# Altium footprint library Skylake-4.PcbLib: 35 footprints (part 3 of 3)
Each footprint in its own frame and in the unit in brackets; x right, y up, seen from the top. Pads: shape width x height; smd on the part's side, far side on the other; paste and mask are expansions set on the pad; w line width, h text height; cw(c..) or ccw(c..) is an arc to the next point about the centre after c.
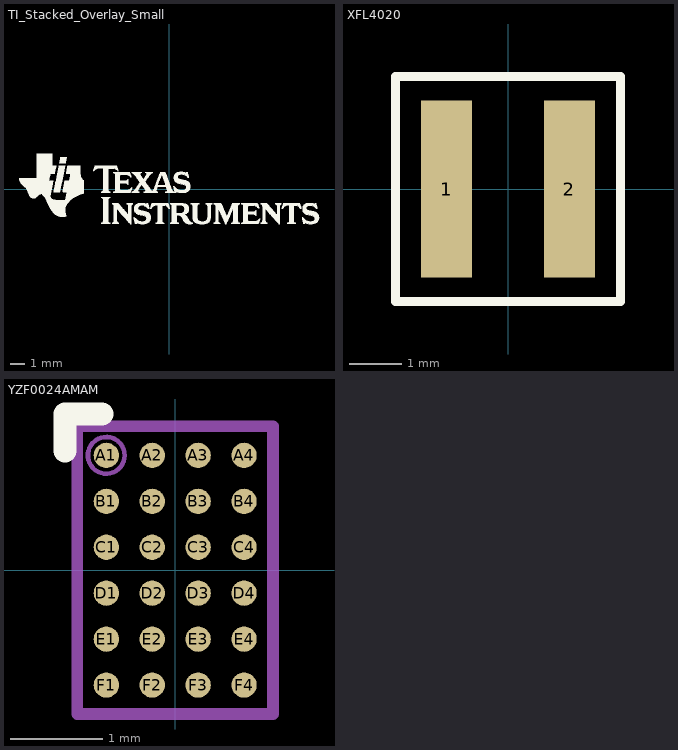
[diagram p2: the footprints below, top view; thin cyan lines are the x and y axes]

## TI_Stacked_Overlay_Small [mm]
Top Overlay:
  drawing of 18 lines, arcs and shapes, not listed

## XFL4020 [mm] "Coilcraft XFL4020 7/18/12"
height 2.1
pads (2):
  rect 0.98x3.4 smd: 1(-1.181,0) 2(1.181,0)
Top Overlay:
  lines w0.17: -2.159,-2.159 -2.159,2.159 2.159,2.159 2.159,-2.159 -2.159,-2.159
Mechanical 5:
  lines w0.1: -2.146,-2.146 -2.146,2.146 2.146,2.146 2.146,-2.146 -2.146,-2.146
  text ".Designator" at 0.504,0.319 h0.76
3D body: height 2.1, standoff 0, extent -2.146,-2.146 2.146,2.146
3D body: height 2.1, standoff 2.03, extent 1.398,-1.269 1.65,1.269

## YZF0024AMAM [mm] "WCSP"
height 0.625
pads (24):
  round 0.275 smd paste-0.15 mask+0.05: A1(-0.75,1.25) A2(-0.25,1.25) A3(0.25,1.25) A4(0.75,1.25) B1(-0.75,0.75) B2(-0.25,0.75) B3(0.25,0.75) B4(0.75,0.75) C1(-0.75,0.25) C2(-0.25,0.25) C3(0.25,0.25) C4(0.75,0.25) D1(-0.75,-0.25) D2(-0.25,-0.25) D3(0.25,-0.25) D4(0.75,-0.25) E1(-0.75,-0.75) E2(-0.25,-0.75) E3(0.25,-0.75) E4(0.75,-0.75) F1(-0.75,-1.25) F2(-0.25,-1.25) F3(0.25,-1.25) F4(0.75,-1.25)
Top Overlay:
  lines w0.254: -1.2,1.3 -1.2,1.7 -0.8,1.7
Top Paste:
  circle w0.05: c0.65,0.35 r0.025
  circle w0.05: c0.85,0.35 r0.025
  circle w0.05: c0.85,0.15 r0.025
  circle w0.05: c0.65,0.15 r0.025
  circle w0.05: c0.15,0.35 r0.025
  circle w0.05: c0.35,0.35 r0.025
  circle w0.05: c0.35,0.15 r0.025
  circle w0.05: c0.15,0.15 r0.025
  circle w0.05: c-0.35,0.35 r0.025
  circle w0.05: c-0.15,0.35 r0.025
  circle w0.05: c-0.15,0.15 r0.025
  circle w0.05: c-0.35,0.15 r0.025
  circle w0.05: c-0.65,0.15 r0.025
  circle w0.05: c-0.85,0.15 r0.025
  circle w0.05: c-0.85,0.35 r0.025
  circle w0.05: c-0.65,0.35 r0.025
  circle w0.05: c-0.65,0.85 r0.025
  circle w0.05: c-0.85,0.85 r0.025
  circle w0.05: c-0.85,0.65 r0.025
  circle w0.05: c-0.65,0.65 r0.025
  circle w0.05: c-0.35,0.65 r0.025
  circle w0.05: c-0.15,0.65 r0.025
  circle w0.05: c-0.15,0.85 r0.025
  circle w0.05: c-0.35,0.85 r0.025
  circle w0.05: c0.15,0.65 r0.025
  circle w0.05: c0.35,0.65 r0.025
  circle w0.05: c0.35,0.85 r0.025
  circle w0.05: c0.15,0.85 r0.025
  circle w0.05: c0.65,0.65 r0.025
  circle w0.05: c0.85,0.65 r0.025
  circle w0.05: c0.85,0.85 r0.025
  circle w0.05: c0.65,0.85 r0.025
  circle w0.05: c-0.65,1.35 r0.025
  circle w0.05: c-0.85,1.35 r0.025
  circle w0.05: c-0.85,1.15 r0.025
  circle w0.05: c-0.65,1.15 r0.025
  circle w0.05: c-0.35,1.15 r0.025
  circle w0.05: c-0.15,1.15 r0.025
  circle w0.05: c-0.15,1.35 r0.025
  circle w0.05: c-0.35,1.35 r0.025
  circle w0.05: c0.15,1.15 r0.025
  circle w0.05: c0.35,1.15 r0.025
  circle w0.05: c0.35,1.35 r0.025
  circle w0.05: c0.15,1.35 r0.025
  circle w0.05: c0.65,1.15 r0.025
  circle w0.05: c0.85,1.15 r0.025
  circle w0.05: c0.85,1.35 r0.025
  circle w0.05: c0.65,1.35 r0.025
  circle w0.05: c0.65,-1.35 r0.025
  circle w0.05: c0.85,-1.35 r0.025
  circle w0.05: c0.85,-1.15 r0.025
  circle w0.05: c0.65,-1.15 r0.025
  circle w0.05: c0.15,-1.35 r0.025
  circle w0.05: c0.35,-1.35 r0.025
  circle w0.05: c0.35,-1.15 r0.025
  circle w0.05: c0.15,-1.15 r0.025
  circle w0.05: c-0.35,-1.35 r0.025
  circle w0.05: c-0.15,-1.35 r0.025
  circle w0.05: c-0.15,-1.15 r0.025
  circle w0.05: c-0.35,-1.15 r0.025
  circle w0.05: c-0.65,-1.15 r0.025
  circle w0.05: c-0.85,-1.15 r0.025
  circle w0.05: c-0.85,-1.35 r0.025
  circle w0.05: c-0.65,-1.35 r0.025
  circle w0.05: c0.65,-0.85 r0.025
  circle w0.05: c0.85,-0.85 r0.025
  circle w0.05: c0.85,-0.65 r0.025
  circle w0.05: c0.65,-0.65 r0.025
  circle w0.05: c0.15,-0.85 r0.025
  circle w0.05: c0.35,-0.85 r0.025
  circle w0.05: c0.35,-0.65 r0.025
  circle w0.05: c0.15,-0.65 r0.025
  circle w0.05: c-0.35,-0.85 r0.025
  circle w0.05: c-0.15,-0.85 r0.025
  circle w0.05: c-0.15,-0.65 r0.025
  circle w0.05: c-0.35,-0.65 r0.025
  circle w0.05: c-0.65,-0.65 r0.025
  circle w0.05: c-0.85,-0.65 r0.025
  circle w0.05: c-0.85,-0.85 r0.025
  circle w0.05: c-0.65,-0.85 r0.025
  circle w0.05: c-0.65,-0.35 r0.025
  circle w0.05: c-0.85,-0.35 r0.025
  circle w0.05: c-0.85,-0.15 r0.025
  circle w0.05: c-0.65,-0.15 r0.025
  circle w0.05: c-0.35,-0.15 r0.025
  circle w0.05: c-0.15,-0.15 r0.025
  circle w0.05: c-0.15,-0.35 r0.025
  circle w0.05: c-0.35,-0.35 r0.025
  circle w0.05: c0.15,-0.15 r0.025
  circle w0.05: c0.35,-0.15 r0.025
  circle w0.05: c0.35,-0.35 r0.025
  circle w0.05: c0.15,-0.35 r0.025
  circle w0.05: c0.65,-0.15 r0.025
  circle w0.05: c0.85,-0.15 r0.025
  circle w0.05: c0.85,-0.35 r0.025
  circle w0.05: c0.65,-0.35 r0.025
  rectangle: 0.6,0.15 0.9,0.35
  region: 0.85,0.1 0.85,0.4 0.65,0.4 0.65,0.1
  rectangle: 0.1,0.15 0.4,0.35
  region: 0.35,0.1 0.35,0.4 0.15,0.4 0.15,0.1
  rectangle: -0.4,0.15 -0.1,0.35
  region: -0.15,0.1 -0.15,0.4 -0.35,0.4 -0.35,0.1
  region: -0.65,0.1 -0.65,0.4 -0.85,0.4 -0.85,0.1
  region: -0.6,0.35 -0.9,0.35 -0.9,0.15 -0.6,0.15
  region: -0.6,0.85 -0.9,0.85 -0.9,0.65 -0.6,0.65
  region: -0.65,0.6 -0.65,0.9 -0.85,0.9 -0.85,0.6
  region: -0.15,0.6 -0.15,0.9 -0.35,0.9 -0.35,0.6
  rectangle: -0.4,0.65 -0.1,0.85
  region: 0.35,0.6 0.35,0.9 0.15,0.9 0.15,0.6
  rectangle: 0.1,0.65 0.4,0.85
  region: 0.85,0.6 0.85,0.9 0.65,0.9 0.65,0.6
  rectangle: 0.6,0.65 0.9,0.85
  region: -0.6,1.35 -0.9,1.35 -0.9,1.15 -0.6,1.15
  region: -0.65,1.1 -0.65,1.4 -0.85,1.4 -0.85,1.1
  region: -0.15,1.1 -0.15,1.4 -0.35,1.4 -0.35,1.1
  rectangle: -0.4,1.15 -0.1,1.35
  region: 0.35,1.1 0.35,1.4 0.15,1.4 0.15,1.1
  rectangle: 0.1,1.15 0.4,1.35
  region: 0.85,1.1 0.85,1.4 0.65,1.4 0.65,1.1
  rectangle: 0.6,1.15 0.9,1.35
  rectangle: 0.6,-1.35 0.9,-1.15
  region: 0.65,-1.1 0.65,-1.4 0.85,-1.4 0.85,-1.1
  rectangle: 0.1,-1.35 0.4,-1.15
  region: 0.15,-1.1 0.15,-1.4 0.35,-1.4 0.35,-1.1
  rectangle: -0.4,-1.35 -0.1,-1.15
  region: -0.35,-1.1 -0.35,-1.4 -0.15,-1.4 -0.15,-1.1
  region: -0.85,-1.1 -0.85,-1.4 -0.65,-1.4 -0.65,-1.1
  region: -0.6,-1.15 -0.9,-1.15 -0.9,-1.35 -0.6,-1.35
  rectangle: 0.6,-0.85 0.9,-0.65
  region: 0.65,-0.6 0.65,-0.9 0.85,-0.9 0.85,-0.6
  rectangle: 0.1,-0.85 0.4,-0.65
  region: 0.15,-0.6 0.15,-0.9 0.35,-0.9 0.35,-0.6
  rectangle: -0.4,-0.85 -0.1,-0.65
  region: -0.35,-0.6 -0.35,-0.9 -0.15,-0.9 -0.15,-0.6
  region: -0.85,-0.6 -0.85,-0.9 -0.65,-0.9 -0.65,-0.6
  region: -0.6,-0.65 -0.9,-0.65 -0.9,-0.85 -0.6,-0.85
  region: -0.6,-0.15 -0.9,-0.15 -0.9,-0.35 -0.6,-0.35
  region: -0.85,-0.1 -0.85,-0.4 -0.65,-0.4 -0.65,-0.1
  region: -0.35,-0.1 -0.35,-0.4 -0.15,-0.4 -0.15,-0.1
  rectangle: -0.4,-0.35 -0.1,-0.15
  region: 0.15,-0.1 0.15,-0.4 0.35,-0.4 0.35,-0.1
  rectangle: 0.1,-0.35 0.4,-0.15
  region: 0.65,-0.1 0.65,-0.4 0.85,-0.4 0.85,-0.1
  rectangle: 0.6,-0.35 0.9,-0.15
Mechanical 5:
  circle w0.05: c-0.75,1.25 r0.2
  lines w0.127: -1.065,-1.565 -1.065,1.565 1.065,1.565 1.065,-1.565 -1.065,-1.565
3D body: height 0.63, standoff 0, extent -1.064,-1.564 1.064,1.564
3D body: height 0.63, standoff 0.5, extent -0.953,1.047 -0.547,1.453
